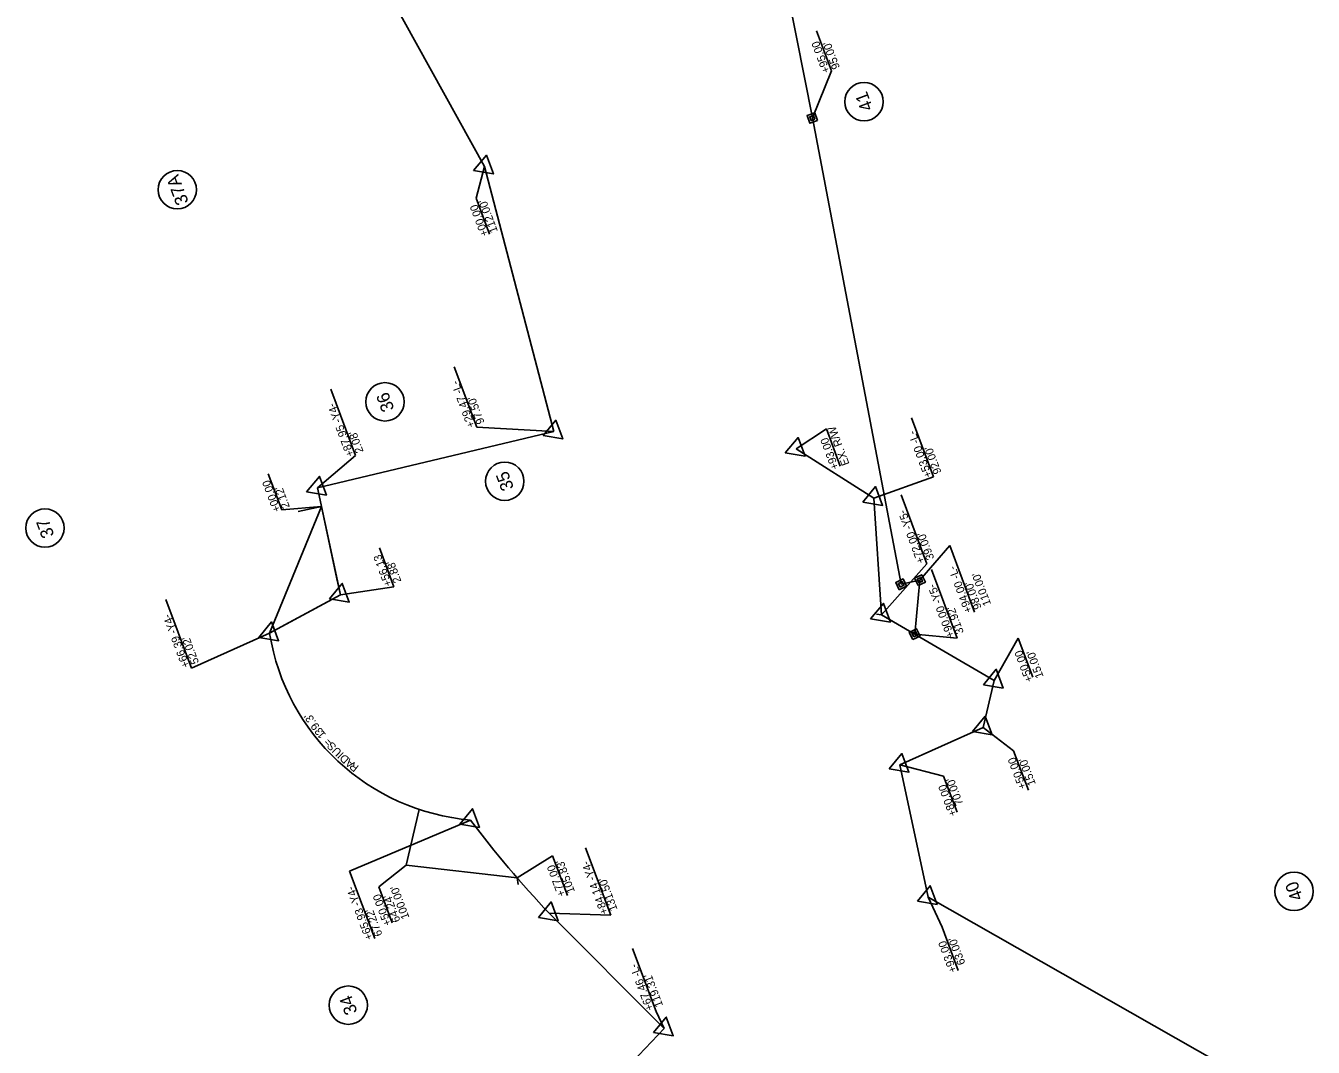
# Model space of a CAD drawing. Extents: x 474184 to 481900, y 489262 to 505659.
# Drawn here: x 478002 to 478806, y 494764 to 495402 of the extents above; entities that cross this region are included whole.
import ezdxf

# ---------------------------------------------------------------- set-up
doc = ezdxf.new("R2010")
doc.units = 0
for name, color, linetype in [('Prop Drainage Structure Drop Inlet Grate 2 Wide Slots and Sag Grates 840 22 CELL', 7, 'Continuous'), ('Prop Drainage Structure Outlet Berm Ditch 850 10 Label', 7, 'Continuous'), ('Prop Drainage Structure Pipe CSP 15in', 7, 'Continuous'), ('Prop Drainage Structure Pipe RCP 18in Class IV', 7, 'Continuous'), ('Prop Drainage Structure Pipe RCP 18in Class IV Label', 7, 'Continuous'), ('Prop Drainage Structure Pipe RCP 24in Class III', 7, 'Continuous'), ('Prop Drainage Structure Pipe Side Drain 15in Label', 7, 'Continuous'), ('Prop Drainage Structure Pipe Stub Out CELL', 7, 'Continuous'), ('Prop Drainage Structure Plot Symbol 50 Scale', 7, 'Continuous'), ('Prop Earthen Structure Base Ditch Lateral Detail Label', 7, 'Continuous'), ('Prop Earthen Structure False Sump CELL', 7, 'Continuous'), ('Prop Earthen Structure False Sump Label', 7, 'Continuous'), ('Sheet Plot Border Outside CELL', 7, 'Continuous'), ('Sheet Sticker Incomplete CELL', 7, 'Continuous')]:
    doc.layers.add(name, color=color, linetype=linetype)

msp = doc.modelspace()

# ---------------------------------------------------------------- linework, layer by layer
at = {"layer": 'Prop Drainage Structure Drop Inlet Grate 2 Wide Slots and Sag Grates 840 22 CELL'}
msp.add_line((478153.86, 495022.15), (478186.27, 495101.34), dxfattribs=at)
at = {"layer": 'Prop Drainage Structure Outlet Berm Ditch 850 10 Label'}
for p, q in [((478492.88, 495344.14), (478434.35, 495641.7)), ((478548.34, 495052.78), (478492.88, 495344.14)), ((478560.06, 495055.35), (478548.34, 495052.78)), ((478556.8, 495021.6), (478560.06, 495055.35))]:
    msp.add_line(p, q, dxfattribs=at)
at = {"layer": 'Prop Drainage Structure Pipe CSP 15in'}
for p, q in [((478525.14, 495354.32), (478525.14, 495354.32)), ((478096.18, 495299.32), (478096.18, 495299.32)), ((478225.91, 495166.79), (478225.91, 495166.79)), ((478300.74, 495117.17), (478300.74, 495117.17)), ((478013.52, 495087.93), (478013.52, 495087.93)), ((478793.76, 494860.94), (478793.76, 494860.94)), ((478202.98, 494789.83), (478202.98, 494789.83))]:
    msp.add_line(p, q, dxfattribs=at)
for centre in [(478525.14, 495354.32), (478096.18, 495299.32), (478225.91, 495166.79), (478300.74, 495117.17), (478013.52, 495087.93), (478793.76, 494860.94), (478202.98, 494789.83)]:
    msp.add_circle(centre, 12, dxfattribs=at)
at = {"layer": 'Prop Drainage Structure Pipe RCP 18in Class IV'}
for p, q in [((478492.88, 495344.14), (478492.88, 495344.14)), ((478288.06, 495313.78), (478288.06, 495313.78)), ((478331.41, 495148.21), (478331.41, 495148.21)), ((478482.74, 495137.39), (478482.74, 495137.39)), ((478183.75, 495113.12), (478183.75, 495113.12)), ((478531.18, 495106.69), (478531.18, 495106.69)), ((478548.34, 495052.78), (478548.34, 495052.78)), ((478560.06, 495055.35), (478560.06, 495055.35)), ((478198.06, 495046.26), (478198.06, 495046.26)), ((478536.02, 495033.74), (478536.02, 495033.74)), ((478153.86, 495022.15), (478153.86, 495022.15)), ((478556.8, 495021.6), (478556.8, 495021.6)), ((478606.5, 494992.58), (478606.5, 494992.58)), ((478599.66, 494963.37), (478599.66, 494963.37)), ((478547.61, 494939.94), (478547.61, 494939.94)), ((478279.36, 494905.49), (478279.36, 494905.49)), ((478565.24, 494857.34), (478565.24, 494857.34)), ((478328.5, 494847.21), (478328.5, 494847.21)), ((478400.39, 494775.31), (478400.39, 494775.31))]:
    msp.add_line(p, q, dxfattribs=at)
for points in [[(478281.29, 495311.27), (478289.26, 495320.88), (478293.62, 495309.19)], [(478324.65, 495145.7), (478332.61, 495155.31), (478336.98, 495143.62)], [(478475.97, 495134.88), (478483.94, 495144.49), (478488.3, 495132.8)], [(478176.98, 495110.61), (478184.95, 495120.22), (478189.31, 495108.53)], [(478524.42, 495104.19), (478532.38, 495113.79), (478536.74, 495102.1)], [(478191.3, 495043.75), (478199.26, 495053.36), (478203.62, 495041.67)], [(478529.26, 495031.23), (478537.22, 495040.83), (478541.59, 495029.14)], [(478147.1, 495019.64), (478155.06, 495029.24), (478159.43, 495017.55)], [(478599.73, 494990.07), (478607.7, 494999.68), (478612.06, 494987.99)], [(478592.89, 494960.86), (478600.86, 494970.47), (478605.22, 494958.78)], [(478540.85, 494937.43), (478548.81, 494947.04), (478553.18, 494935.35)], [(478272.59, 494902.98), (478280.56, 494912.59), (478284.92, 494900.9)], [(478558.48, 494854.83), (478566.44, 494864.44), (478570.8, 494852.75)], [(478321.74, 494844.7), (478329.7, 494854.31), (478334.06, 494842.62)], [(478393.62, 494772.8), (478401.59, 494782.4), (478405.95, 494770.71)]]:
    msp.add_lwpolyline(points, close=True, dxfattribs=at)
at = {"layer": 'Prop Drainage Structure Pipe RCP 18in Class IV Label'}
for points in [[(478496.15, 495342.65), (478491.38, 495340.87), (478489.6, 495345.64), (478494.37, 495347.42)], [(478494.51, 495343.4), (478492.13, 495342.51), (478491.24, 495344.89), (478493.62, 495345.78)], [(478558.89, 495051.95), (478556.66, 495056.53), (478561.24, 495058.76), (478563.47, 495054.18)], [(478559.48, 495053.65), (478558.36, 495055.94), (478560.65, 495057.06), (478561.77, 495054.77)], [(478547.17, 495049.37), (478544.94, 495053.95), (478549.52, 495056.18), (478551.75, 495051.61)], [(478547.76, 495051.08), (478546.64, 495053.36), (478548.93, 495054.48), (478550.05, 495052.19)], [(478555.63, 495018.2), (478553.4, 495022.77), (478557.98, 495025), (478560.21, 495020.43)], [(478556.22, 495019.9), (478555.1, 495022.19), (478557.39, 495023.3), (478558.51, 495021.01)]]:
    msp.add_lwpolyline(points, close=True, dxfattribs=at)
at = {"layer": 'Prop Drainage Structure Pipe RCP 24in Class III'}
for p, q in [((478186.27, 495101.34), (478153.86, 495022.15)), ((478198.06, 495046.26), (478186.27, 495101.34)), ((478153.86, 495022.15), (478198.06, 495046.26))]:
    msp.add_line(p, q, dxfattribs=at)
at = {"layer": 'Prop Drainage Structure Pipe Side Drain 15in Label'}
for p, q in [((478288.06, 495313.78), (478071.24, 495705.32)), ((478331.41, 495148.21), (478288.06, 495313.78)), ((478331.41, 495148.21), (478183.75, 495113.12)), ((478531.18, 495106.69), (478482.74, 495137.39)), ((478198.06, 495046.26), (478183.75, 495113.12)), ((478536.02, 495033.74), (478531.18, 495106.69)), ((478153.86, 495022.15), (478198.06, 495046.26)), ((478606.5, 494992.58), (478536.02, 495033.74)), ((478599.66, 494963.37), (478606.5, 494992.58)), ((478547.61, 494939.94), (478599.66, 494963.37)), ((478565.24, 494857.34), (478547.61, 494939.94)), ((478775.2, 494737.87), (478565.24, 494857.34)), ((478400.39, 494775.31), (478328.5, 494847.21))]:
    msp.add_line(p, q, dxfattribs=at)
msp.add_lwpolyline([(478372.69, 494746.09), (478400.39, 494775.31)], dxfattribs=at)
for centre, radius, start, end in [((478291.39, 495044.26), 139.29, 189.13628, 265.04526), ((478820.37, 495311.81), 676.6, 216.90763, 223.3671)]:
    msp.add_arc(centre, radius, start, end, dxfattribs=at)
at = {"layer": 'Prop Drainage Structure Pipe Stub Out CELL'}
for p, q in [((478239.1, 494877.33), (478247.26, 494912.15)), ((478308.53, 494869.3), (478239.1, 494877.33))]:
    msp.add_line(p, q, dxfattribs=at)
at = {"layer": 'Prop Drainage Structure Plot Symbol 50 Scale'}
for p, q in [((478282.82, 495294), (478291.23, 495271.47)), ((478269.21, 495188.59), (478283.22, 495151.06)), ((478192.04, 495174.73), (478207.56, 495133.16)), ((478554.9, 495156.71), (478568.64, 495119.92)), ((478283.22, 495151.06), (478331.41, 495148.21)), ((478501.64, 495149.89), (478510.33, 495126.6)), ((478183.75, 495113.12), (478207.56, 495133.16)), ((478548.28, 495108.76), (478564.41, 495065.53)), ((478222.45, 495075.59), (478231.52, 495051.27)), ((478536.02, 495033.74), (478564.41, 495065.53)), ((478198.06, 495046.26), (478231.52, 495051.27)), ((478089.09, 495043.37), (478105.1, 495000.46)), ((478621.41, 495019.1), (478630.49, 494994.79)), ((478618.59, 494948.82), (478627.81, 494924.12)), ((478574.84, 494932.93), (478583.25, 494910.4)), ((478279.36, 494905.49), (478203.79, 494873.53)), ((478351.19, 494888.06), (478366.89, 494846)), ((478203.79, 494873.53), (478219.51, 494831.44)), ((478328.5, 494847.21), (478366.89, 494846)), ((478573.86, 494838.48), (478583.93, 494811.49)), ((478380.59, 494825.29), (478395.29, 494785.91)), ((478395.29, 494785.91), (478400.39, 494775.31))]:
    msp.add_line(p, q, dxfattribs=at)
for points in [[(478282.82, 495294), (478288.06, 495313.78)], [(478501.64, 495149.89), (478482.74, 495137.39)], [(478568.64, 495119.92), (478531.18, 495106.69)], [(478532.98, 495034.06), (478536.02, 495033.74)], [(478105.1, 495000.46), (478153.86, 495022.15)], [(478621.41, 495019.1), (478606.5, 494992.58)], [(478618.59, 494948.82), (478599.66, 494963.37)], [(478574.84, 494932.93), (478547.61, 494939.94)], [(478573.86, 494838.48), (478565.24, 494857.34)]]:
    msp.add_lwpolyline(points, dxfattribs=at)
at = {"layer": 'Prop Earthen Structure Base Ditch Lateral Detail Label'}
for p, q in [((478495.49, 495398.5), (478504.78, 495373.59)), ((478578.67, 495076.97), (478560.06, 495055.35)), ((478594.17, 495035.44), (478578.67, 495076.97)), ((478583.35, 495019.2), (478567.34, 495062.09)), ((478556.8, 495021.6), (478583.35, 495019.2))]:
    msp.add_line(p, q, dxfattribs=at)
msp.add_lwpolyline([(478504.78, 495373.59), (478492.88, 495344.14)], dxfattribs=at)
at = {"layer": 'Prop Earthen Structure False Sump CELL'}
msp.add_line((478152.99, 495121.74), (478161.4, 495099.21), dxfattribs=at)
msp.add_lwpolyline([(478161.4, 495099.21), (478186.27, 495101.34)], dxfattribs=at)
at = {"layer": 'Prop Earthen Structure False Sump Label'}
for p, q in [((478330.59, 494883.03), (478308.53, 494869.3)), ((478330.59, 494883.03), (478339.83, 494858.29)), ((478222.05, 494863.81), (478230.46, 494841.28))]:
    msp.add_line(p, q, dxfattribs=at)
msp.add_lwpolyline([(478222.05, 494863.81), (478239.1, 494877.33)], dxfattribs=at)
at = {"layer": 'Sheet Plot Border Outside CELL'}
for p, q in [((478186.27, 495101.34), (478153.86, 495022.15)), ((478195.93, 495056.22), (478186.27, 495101.34)), ((478198.06, 495046.26), (478195.93, 495056.22)), ((478166.1, 495028.82), (478198.06, 495046.26)), ((478153.86, 495022.15), (478166.1, 495028.82))]:
    msp.add_line(p, q, dxfattribs=at)
at = {"layer": 'Sheet Sticker Incomplete CELL'}
for p, q in [((478171.78, 495098.19), (478186.27, 495101.34)), ((478309.21, 494865.19), (478308.53, 494869.3))]:
    msp.add_line(p, q, dxfattribs=at)

# ---------------------------------------------------------------- texts
at = {"layer": 'Prop Drainage Structure Pipe CSP 15in'}
for s, p in [('41', (478530.96, 495350.15)), ('37A', (478103.35, 495291.55)), ('36', (478231.85, 495162.31)), ('35', (478306.57, 495112.98)), ('37', (478019.46, 495083.45)), ('40', (478799.58, 494856.78)), ('34', (478208.84, 494785.58))]:
    msp.add_text(s, height=8, rotation=110.46898, dxfattribs=at).set_placement(p)
at = {"layer": 'Prop Drainage Structure Plot Symbol 50 Scale'}
for s, rotation, p in [("112.00'", 110.46898, (478296.49, 495273.44)), ('+00.00', 110.46898, (478290.64, 495271.25)), ('+29.47 -L-', 110.46898, (478282.31, 495151.71)), ('+87.95 -Y4-', 110.46898, (478206.74, 495133.57)), ("97.50'", 110.46898, (478288.17, 495153.89)), ("2.08'", 110.46898, (478212.6, 495135.75)), ('EX. R/W', 110.46898, (478516.12, 495128.01)), ('+53.00 -L-', 110.46898, (478567.74, 495120.52)), ('+93.00', 110.46898, (478509.56, 495125.56)), ("92.00'", 110.46898, (478573.6, 495122.71)), ('+72.00 -Y5-', 110.46898, (478563.24, 495066.85)), ("39.00'", 110.46898, (478569.1, 495069.04)), ('+56.13 ', 110.46898, (478230.4, 495052.52)), ("2.88'", 110.46898, (478236.25, 495054.7)), ('+66.39 -Y4- ', 110.46898, (478103.98, 495001.71)), ("52.02'", 110.46898, (478109.83, 495003.89)), ('+50.00', 110.46898, (478630.85, 494992.71)), ("15.00'", 110.46898, (478637.41, 494995.16)), ("'", 122.25388, (478179.85, 494971.71)), ('3', 123.89527, (478181.98, 494968.55)), ('9', 126.35737, (478185.33, 494963.92)), ('.', 124.71597, (478183.07, 494966.99)), ('3', 127.99876, (478187.68, 494960.91)), ('1', 129.14334, (478189.36, 494958.86)), ('=', 131.86013, (478193.53, 494954.12)), ('S', 133.3506, (478195.9, 494951.6)), ('U', 135.37247, (478199.23, 494948.29)), ('I', 136.146, (478200.54, 494947.06)), ('D', 138.1553, (478204, 494943.93)), ('+50.00 ', 110.46898, (478626.67, 494925.86)), ('A', 139.95391, (478207.19, 494941.24)), ('R', 141.47582, (478209.96, 494939.04)), ("15.00'", 110.46898, (478632.53, 494928.04)), ("70.00'", 110.46898, (478587.26, 494915.62)), ('+80.00', 110.46898, (478583.22, 494908.91)), ('+84.14 -Y4-', 110.46898, (478365.43, 494847.55)), ("131.50'", 110.46898, (478371.28, 494849.73)), ('+65.93 -Y4-', 110.46898, (478218.55, 494831.62)), ("67.22'", 110.46898, (478224.41, 494833.8)), ('+93.00', 110.46898, (478583.22, 494811.23)), ("63.00'", 110.46898, (478588.55, 494815.95)), ('+67.46 -L-', 110.46898, (478393.82, 494787.46)), ("119.31'", 110.46898, (478399.68, 494789.64))]:
    msp.add_text(s, height=5, rotation=rotation, dxfattribs=at).set_placement(p)
at = {"layer": 'Prop Earthen Structure Base Ditch Lateral Detail Label'}
for s, p in [('+95.00', (478504.07, 495373.33)), ("95.00'", (478510.21, 495375.62)), ('+94.00 -L-', (478592.87, 495036)), ("110.00' ", (478604.58, 495040.37)), ('+90.00 -Y5- ', (478581.72, 495020.51)), ("98.00'", (478598.72, 495038.19)), ("31.92' ", (478587.57, 495022.7))]:
    msp.add_text(s, height=5, rotation=110.46898, dxfattribs=at).set_placement(p)
at = {"layer": 'Prop Earthen Structure False Sump CELL'}
for s, p in [('+00.00', (478160.93, 495099.04)), ("2.12'", (478166.55, 495101.13))]:
    msp.add_text(s, height=5, rotation=110.46898, dxfattribs=at).set_placement(p)
at = {"layer": 'Prop Earthen Structure False Sump Label'}
for s, p in [('+77.00', (478338.79, 494858.69)), ("105.83'", (478344.65, 494860.88)), ('+50.00', (478230.03, 494840.44)), ("64.24' ", (478235.65, 494842.54)), ("100.00'", (478241.27, 494844.64))]:
    msp.add_text(s, height=5, rotation=110.46898, dxfattribs=at).set_placement(p)

doc.saveas('drawing.dxf')
